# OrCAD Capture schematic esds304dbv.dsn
size A; title: ESDS304 Data-Line Surge and ESD Protection Devices for High Speed; rev: 1.0; note: Datasheet: SLVSEG8A    EVM:NA
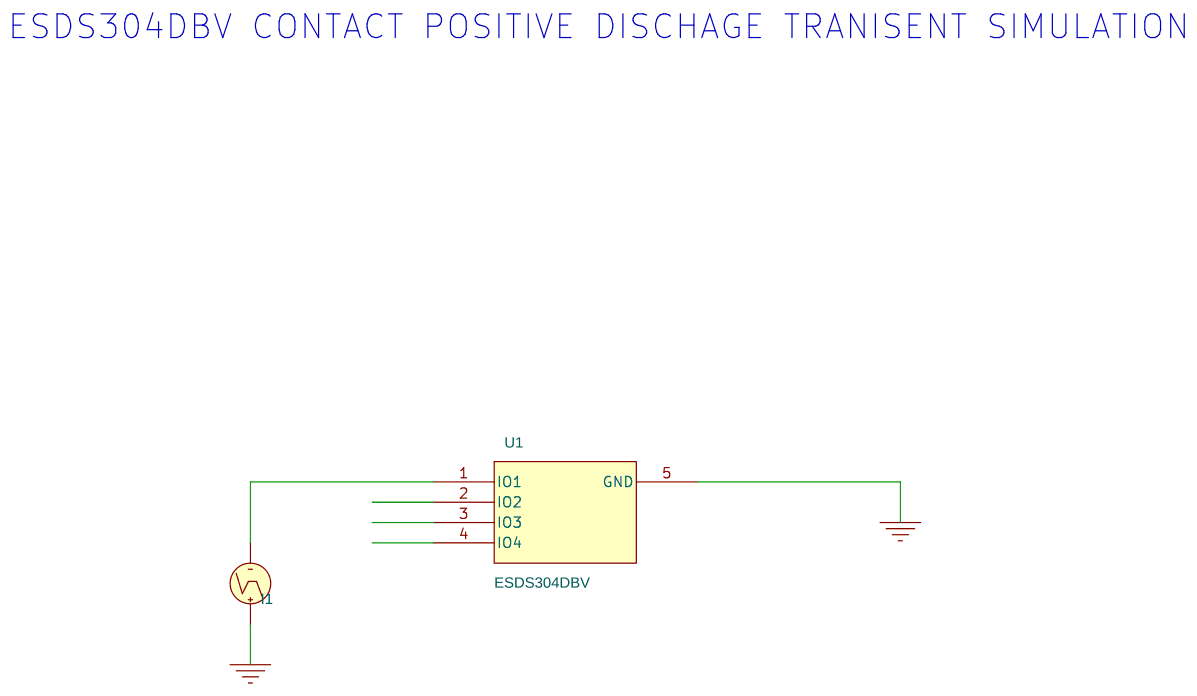
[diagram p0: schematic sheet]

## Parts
I1  IPWL_GENERIC
U1  ESDS304DBV

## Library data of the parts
I1 = IPWL_GENERIC: AppProp: No_reps$POINTS_TYPE_PWL$0$0; FIRST_NPAIRS: 0n 0 0.8n 30 6n 8 9.5n 12.5 10n 13 18n 16 22n 16 25n 16 60n 9 72n 7 82n 5.3 150n 0; PSpiceTemplate: I^@REFDES %+ %- ?DC|DC @DC| ?AC|AC @AC| PWL ?TSF|TIME_SCALE_FACTOR=@TSF| ?VSF|VALUE_SCALE_FACTOR=@VSF| ?REPEAT_VALUE| \n+ REPEAT FOR @REPEAT_VALUE| \n+ @FIRST_NPAIRS ?SECOND_NPAIRS|\n+ @SECOND_NPAIRS ?THIRD_NPAIRS/\n+ @THIRD_NPAIRS/| ?REPEAT_VALUE| \n+ ENDREPEAT|
U1 = ESDS304DBV

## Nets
0: I1.1(+) U1.5(GND)
N00959: I1.2(-) U1.1(IO1)

Not connected (* = marked no-connect by the designer): U1 2(IO2) 3(IO3) 4(IO4)

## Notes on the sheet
- ESDS304DBV CONTACT POSITIVE DISCHAGE TRANISENT SIMULATION
